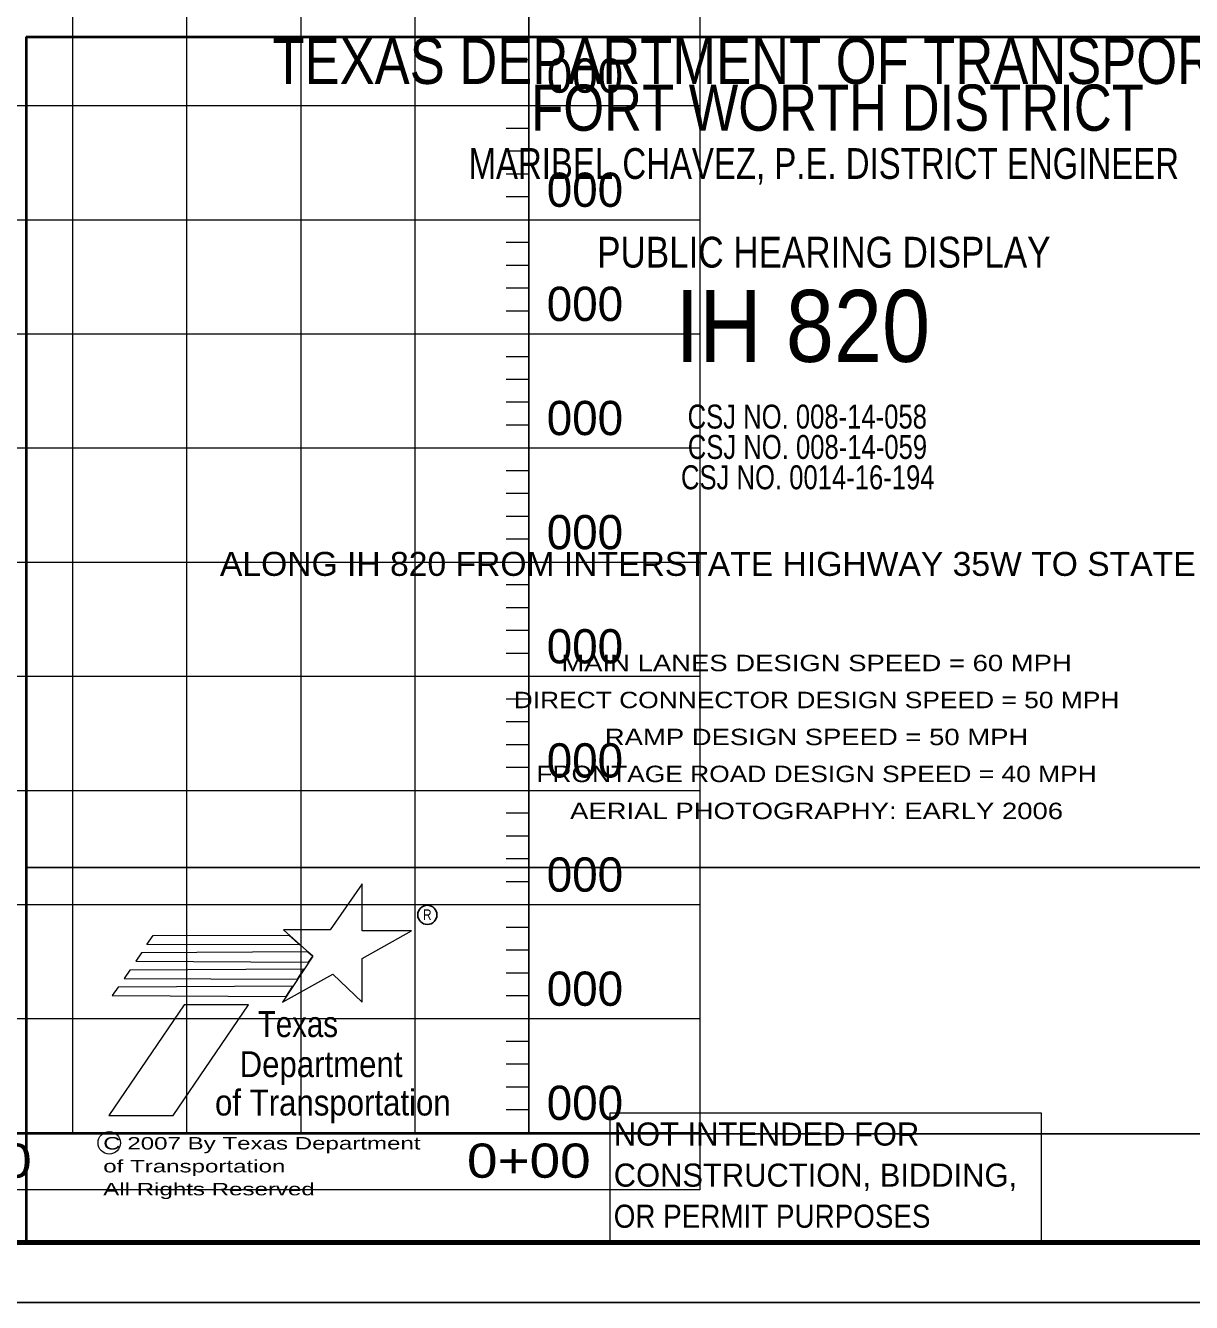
# Model space of a CAD drawing. Extents: x 2246932 to 2264252, y 7095151 to 7098651.
# Drawn here: x 2262650 to 2263672, y 7095151 to 7096270 of the extents above; entities that cross this region are included whole.
import ezdxf
from ezdxf.enums import TextEntityAlignment as Align

# ---------------------------------------------------------------- set-up
doc = ezdxf.new("R2010")
doc.units = 0
doc.header["$LTSCALE"] = 12
for name, color, linetype, lineweight in [('1', 7, 'Continuous', 80), ('2', 7, 'Continuous', 25), ('29', 7, 'Continuous', 13), ('62', 7, 'Continuous', 13), ('63', 7, 'Continuous', 25)]:
    doc.layers.add(name, color=color, linetype=linetype, lineweight=lineweight)
doc.layers.add('22', color=7, linetype='Continuous')

msp = doc.modelspace()

# ---------------------------------------------------------------- linework, layer by layer
at = {"layer": '1', "lineweight": 40}
for q in [(2264052.08, 7096259.77), (2262650.97, 7095203.35)]:
    msp.add_line((2262650.97, 7096259.77), q, dxfattribs=at)
at = {"layer": '1'}
msp.add_line((2247157.09, 7095203.35), (2264052.09, 7095203.35), dxfattribs=at)
at = {"layer": '1', "lineweight": 25}
msp.add_line((2247104.59, 7095150.85), (2264104.59, 7095150.85), dxfattribs=at)
at = {"layer": '2'}
for p, q in [((2262650.97, 7095531.85), (2264052.08, 7095531.85)), ((2262610.97, 7095203.35), (2264052.08, 7095203.35))]:
    msp.add_line(p, q, dxfattribs=at)
at = {"layer": '29'}
msp.add_line((2262897.61, 7095458.06), (2262902.11, 7095454.39), dxfattribs=at)
for points in [[(2262945.39, 7095517.68), (2262917.22, 7095477.25), (2262876.38, 7095477.25), (2262902.11, 7095454.39), (2262875.56, 7095413.96), (2262919.67, 7095438.46), (2262945.39, 7095413.96), (2262945.39, 7095452.34), (2262988.68, 7095476.44), (2262945.39, 7095476.44)], [(2262762.03, 7095472.35), (2262881.28, 7095472.76), (2262891.08, 7095464.19), (2262756.73, 7095464.59)], [(2262897.61, 7095458.06), (2262751.83, 7095457.24), (2262746.92, 7095449.89), (2262898.43, 7095449.08), (2262902.11, 7095454.39)], [(2262894.35, 7095442.95), (2262741.62, 7095442.13), (2262736.71, 7095434.78), (2262888.63, 7095433.97)], [(2262884.55, 7095427.84), (2262731.41, 7095427.03), (2262726.1, 7095419.67), (2262878.83, 7095418.86)], [(2262789.4, 7095411.51), (2262723.24, 7095314.72), (2262779.59, 7095314.72), (2262845.75, 7095411.51)], [(2263162.61, 7095316.87), (2263540.45, 7095316.87), (2263540.45, 7095203.35), (2263162.61, 7095203.35)]]:
    msp.add_lwpolyline(points, close=True, dxfattribs=at)
at = {"layer": '29', "lineweight": 25}
msp.add_circle((2263002.49, 7095490.43), 8.38, dxfattribs=at)
at = {"layer": '29'}
msp.add_circle((2262723.7, 7095290.73), 9.85, dxfattribs=at)
at = {"layer": '62'}
for p, q in [((2262691.45, 7096799.51), (2262691.45, 7095299.51)), ((2262791.45, 7096799.51), (2262791.45, 7095299.51)), ((2262891.45, 7096799.51), (2262891.45, 7095299.51)), ((2262991.45, 7096799.51), (2262991.45, 7095299.51)), ((2263091.45, 7095299.51), (2263091.45, 7096799.51)), ((2263091.45, 7096799.51), (2263091.45, 7095299.51)), ((2263241.45, 7096799.51), (2263241.45, 7095999.51)), ((2263091.45, 7096259.51), (2263071.45, 7096259.51)), ((2263091.45, 7096239.51), (2263071.45, 7096239.51)), ((2263091.45, 7096219.51), (2263071.45, 7096219.51)), ((2263091.45, 7096179.51), (2263071.45, 7096179.51)), ((2263091.45, 7096159.51), (2263071.45, 7096159.51)), ((2263091.45, 7096139.51), (2263071.45, 7096139.51)), ((2263091.45, 7096119.51), (2263071.45, 7096119.51)), ((2263091.45, 7096079.51), (2263071.45, 7096079.51)), ((2263091.45, 7096059.51), (2263071.45, 7096059.51)), ((2263091.45, 7096039.51), (2263071.45, 7096039.51)), ((2263091.45, 7096019.51), (2263071.45, 7096019.51)), ((2263241.45, 7095999.51), (2263241.45, 7095249.51)), ((2263091.45, 7095979.51), (2263071.45, 7095979.51)), ((2263091.45, 7095959.51), (2263071.45, 7095959.51)), ((2263091.45, 7095939.51), (2263071.45, 7095939.51)), ((2263091.45, 7095919.51), (2263071.45, 7095919.51)), ((2263091.45, 7095879.51), (2263071.45, 7095879.51)), ((2263091.45, 7095859.51), (2263071.45, 7095859.51)), ((2263091.45, 7095839.51), (2263071.45, 7095839.51)), ((2263091.45, 7095819.51), (2263071.45, 7095819.51)), ((2263091.45, 7095779.51), (2263071.45, 7095779.51)), ((2263091.45, 7095759.51), (2263071.45, 7095759.51)), ((2263091.45, 7095739.51), (2263071.45, 7095739.51)), ((2263091.45, 7095719.51), (2263071.45, 7095719.51)), ((2263091.45, 7095679.51), (2263071.45, 7095679.51)), ((2263091.45, 7095659.51), (2263071.45, 7095659.51)), ((2263091.45, 7095639.51), (2263071.45, 7095639.51)), ((2263091.45, 7095619.51), (2263071.45, 7095619.51)), ((2263091.45, 7095579.51), (2263071.45, 7095579.51)), ((2263091.45, 7095559.51), (2263071.45, 7095559.51)), ((2263091.45, 7095539.51), (2263071.45, 7095539.51)), ((2263091.45, 7095519.51), (2263071.45, 7095519.51)), ((2263091.45, 7095479.51), (2263071.45, 7095479.51)), ((2263091.45, 7095459.51), (2263071.45, 7095459.51)), ((2263091.45, 7095439.51), (2263071.45, 7095439.51)), ((2263091.45, 7095419.51), (2263071.45, 7095419.51)), ((2263091.45, 7095379.51), (2263071.45, 7095379.51)), ((2263091.45, 7095359.51), (2263071.45, 7095359.51)), ((2263091.45, 7095339.51), (2263071.45, 7095339.51)), ((2263091.45, 7095319.51), (2263071.45, 7095319.51)), ((2263241.45, 7095299.51), (2247941.45, 7095299.51)), ((2263241.45, 7095249.51), (2247941.45, 7095249.51))]:
    msp.add_line(p, q, dxfattribs=at)
for points in [[(2248091.45, 7096199.51), (2263091.45, 7096199.51), (2263241.45, 7096199.51)], [(2248091.45, 7096099.51), (2263091.45, 7096099.51), (2263241.45, 7096099.51)], [(2248091.45, 7095999.51), (2263091.45, 7095999.51), (2263241.45, 7095999.51)], [(2248091.45, 7095899.51), (2263091.45, 7095899.51), (2263241.45, 7095899.51)], [(2248091.45, 7095799.51), (2263091.45, 7095799.51), (2263241.45, 7095799.51)], [(2248091.45, 7095699.51), (2263091.45, 7095699.51), (2263241.45, 7095699.51)], [(2248091.45, 7095599.51), (2263091.45, 7095599.51), (2263241.45, 7095599.51)], [(2248091.45, 7095499.51), (2263091.45, 7095499.51), (2263241.45, 7095499.51)], [(2248091.45, 7095399.51), (2263091.45, 7095399.51), (2263241.45, 7095399.51)]]:
    msp.add_lwpolyline(points, dxfattribs=at)
at = {"layer": '63'}
msp.add_lwpolyline([(2264252.09, 7095298.54), (2262549.93, 7095298.54), (2262549.93, 7098498.04), (2264252.09, 7098498.04)], close=True, dxfattribs=at)

# ---------------------------------------------------------------- texts
at = {"layer": '1'}
for s, width, p in [('MAIN LANES DESIGN SPEED = 60 MPH', 1.25, (2263343.63, 7095703.94)), ('DIRECT CONNECTOR DESIGN SPEED = 50 MPH', 1.2, (2263343.63, 7095671.54)), ('RAMP DESIGN SPEED = 50 MPH', 1.25, (2263343.63, 7095639.14)), ('FRONTAGE ROAD DESIGN SPEED = 40 MPH', 1.2, (2263343.63, 7095606.74)), ('AERIAL PHOTOGRAPHY: EARLY 2006', 1.25, (2263343.63, 7095574.34))]:
    msp.add_text(s, height=14.4, dxfattribs=dict(at, width=width)).set_placement(p, align=Align.CENTER)
at = {"layer": '22'}
for p in [(2263107.14, 7096210.78), (2263107.14, 7096110.78), (2263107.14, 7096010.78), (2263107.13, 7095910.78), (2263107.13, 7095810.78), (2263107.13, 7095710.78), (2263107.13, 7095610.78), (2263107.13, 7095510.78), (2263107.13, 7095410.78), (2263107.13, 7095310.78)]:
    msp.add_text('000', height=30, dxfattribs=at).set_placement(p)
at = {"layer": '22', "width": 1.2}
for p in [(2262601.51, 7095260.11), (2263091.44, 7095260.11), (2263091.44, 7095260.11)]:
    msp.add_text('0+00', height=30, dxfattribs=at).set_placement(p, align=Align.CENTER)
at = {"layer": '29'}
for s, height, width, p in [('TEXAS DEPARTMENT OF TRANSPORTATION', 40.5, 0.85, (2263364.25, 7096218.46)), ('FORT WORTH DISTRICT', 40.5, 0.85, (2263361.99, 7096177.46)), ('MARIBEL CHAVEZ, P.E. DISTRICT ENGINEER', 27, 0.8, (2263349.94, 7096135.26)), ('PUBLIC HEARING DISPLAY', 27, 0.85, (2263350, 7096057.56)), ('IH 820', 63, 0.9, (2263331.51, 7095974.96)), ('CSJ NO. 008-14-058', 21, 0.8, (2263335.5, 7095916.52)), ('CSJ NO. 008-14-059', 21, 0.8, (2263335.63, 7095889.92)), ('CSJ NO. 0014-16-194', 21, 0.8, (2263335.93, 7095863.32)), ('ALONG IH 820 FROM INTERSTATE HIGHWAY 35W TO STATE HIGHWAY 26', 21, 1.05, (2263343.32, 7095787.46))]:
    msp.add_text(s, height=height, dxfattribs=dict(at, width=width)).set_placement(p, align=Align.CENTER)
for s, height, width, p in [('R', 9.26, 0.85, (2262998.62, 7095485.99)), ('Texas', 22.7, 0.85, (2262853.91, 7095383.38)), ('Department ', 22.7, 0.9, (2262837.94, 7095348.29)), ('of Transportation', 22.7, 0.9, (2262816.4, 7095314.65)), ('C 2007 By Texas Department ', 10.89, 1.45, (2262718.39, 7095284.88)), ('of Transportation', 10.89, 1.45, (2262718.39, 7095264.8)), ('All Rights Reserved', 10.89, 1.45, (2262718.39, 7095244.71)), ('OR PERMIT PURPOSES', 20.25, 0.9, (2263165.86, 7095216.29))]:
    msp.add_text(s, height=height, dxfattribs=dict(at, width=width)).set_placement(p)
for s, p in [('NOT INTENDED FOR', (2263165.86, 7095288.29)), ('CONSTRUCTION, BIDDING,', (2263165.86, 7095252.29))]:
    msp.add_text(s, height=20.25, dxfattribs=at).set_placement(p)

doc.saveas('drawing.dxf')
